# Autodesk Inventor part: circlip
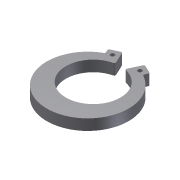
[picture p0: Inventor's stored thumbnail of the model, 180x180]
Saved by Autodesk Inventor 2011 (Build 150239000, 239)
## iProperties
Created: 2008-06
Part Number: circlip
Document SubType Name: Modeling
Designer: CADCIM
Density: 1 g/cm^3
Author: CADCIM
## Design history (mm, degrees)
sketch "Sketch1"
  geometry: L1 (-34.277, -4)-(34.277, -4); L2 (0, 41.942)-(0, -37.008); L3 (-3.5, 19.691)-(-8.149, 29.661); L4 (-8.149, 29.661)-(-15.399, 26.28); L5 (-15.399, 26.28)-(-13.72, 22.679); L6 (3.5, 19.691)-(8.149, 29.661); L7 (8.149, 29.661)-(15.399, 26.28); L8 (15.399, 26.28)-(13.72, 22.679); C1 r 1.5 at (-10.047, 24.267); C2 r 1.5 at (10.047, 24.267); A1 r 20 centre (0, 0) between (-3.5, 19.691) and (3.5, 19.691); A2 r 30 centre (0, -4) between (-13.72, 22.679) and (13.72, 22.679); 1 further point
  constraints: 16 end point, 5 point on circle, 5 symmetric about line, 4 centre point, 3 perpendicular, 2 midpoint, 2 point on line, 1 coincident, 1 horizontal, 2 other
  dimensions: "d0" = 40 diameter of A1; "d1" = 4 distance from line of L1 point (0, 0); "d2" = 60 diameter of A2; "d3" = 3 diameter of C1; "d16" = 8 distance of L3.end L4.end; "d17" = 11 distance of L6.start L6.end; "d20" = 4 distance from line of L3 C1.centre; "d21" = 50 deg angle of L3 L6; "d23" = 7 distance of L6.start L3.start
extrude "Extrusion1" new body sketch "Sketch1" distance "d5" = 8; taper "d6" = 0 deg
fillet "Fillet1" dims "d7" = 1
body "Solid1"
other parameters: "d13" = 0
